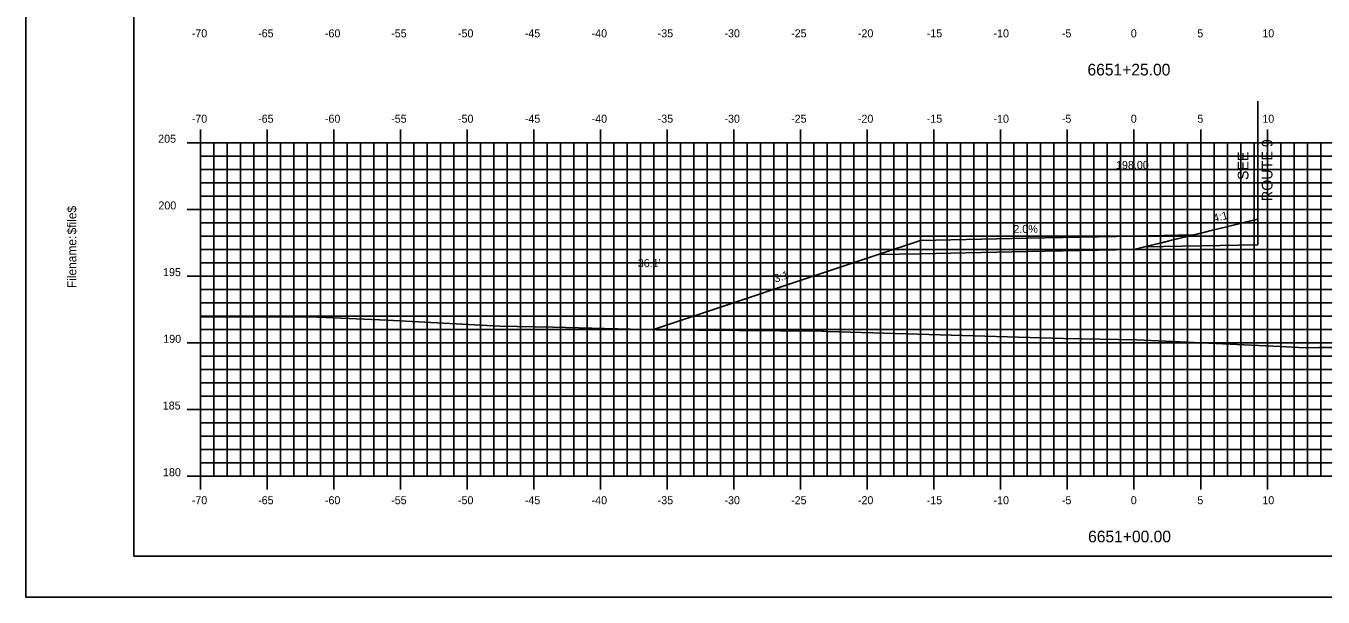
# Model space of a CAD drawing. Extents: x 1723543 to 1723714, y 458501 to 458611.
# Drawn here: x 1723542.7 to 1723640, y 458501.2 to 458544 of the extents above; entities that cross this region are included whole.
import ezdxf

# ---------------------------------------------------------------- set-up
doc = ezdxf.new("R2010")
doc.units = 0
for name, color, linetype in [('ANNOTATION', 7, 'Continuous'), ('BORDER', 7, 'Continuous'), ('D_Roadway_Centerline', 7, 'Continuous'), ('D_Roadway_Centerline_Text', 7, 'Continuous'), ('D_Roadway_Drive_Gravel', 7, 'Continuous'), ('D_Roadway_Edge_Shoulder', 7, 'Continuous'), ('D_Roadway_SlopeLines', 7, 'Continuous'), ('D_Roadway_SubGrade', 7, 'Continuous'), ('D_Text_Standard', 7, 'Continuous'), ('H_V ANNOTATION', 7, 'Continuous'), ('MAJOR', 7, 'Continuous'), ('MINOR', 7, 'Continuous'), ('PLOT BOUNDARY', 7, 'Continuous'), ('S_Roadway_Centerline', 7, 'Continuous')]:
    doc.layers.add(name, color=color, linetype=linetype)

msp = doc.modelspace()

# ---------------------------------------------------------------- linework, layer by layer
msp.add_lwpolyline([(1723589.666, 458521.228), (1723606.594, 458526.871), (1723609.785, 458527.934), (1723617.785, 458528.094), (1723625.785, 458528.254), (1723630.251, 458528.344)])
at = {"layer": 'BORDER'}
msp.add_lwpolyline([(1723550.786, 458504.254), (1723710.786, 458504.254), (1723710.786, 458609.254), (1723550.786, 458609.254)], close=True, dxfattribs=at)
at = {"layer": 'D_Roadway_Centerline'}
msp.add_lwpolyline([(1723625.785, 458527.254), (1723626.585, 458527.449), (1723627.961, 458527.785), (1723628.593, 458527.939), (1723630.323, 458528.361), (1723631.684, 458528.693), (1723632.511, 458528.895), (1723634.424, 458529.362), (1723634.641, 458529.415), (1723635.073, 458529.52)], dxfattribs=at)
at = {"layer": 'D_Roadway_Drive_Gravel'}
msp.add_lwpolyline([(1723625.785, 458528.254), (1723617.785, 458528.094), (1723609.785, 458527.934), (1723606.594, 458526.871), (1723609.785, 458526.934), (1723617.785, 458527.094), (1723625.785, 458527.254), (1723625.785, 458527.254)], dxfattribs=at)
at = {"layer": 'D_Roadway_Edge_Shoulder'}
msp.add_line((1723635.073, 458529.52), (1723635.073, 458529.27), dxfattribs=at)
msp.add_line((1723635.073, 458529.52), (1723635.073, 458529.27), dxfattribs=at)
at = {"layer": 'D_Roadway_SlopeLines'}
for points in [[(1723635.073, 458529.52), (1723625.785, 458527.254)], [(1723635.073, 458529.52), (1723625.785, 458527.254)], [(1723635.073, 458529.52), (1723625.785, 458527.254)], [(1723635.073, 458529.52), (1723625.785, 458527.254)], [(1723635.073, 458529.52), (1723625.785, 458527.254)], [(1723635.073, 458529.52), (1723625.785, 458527.254)], [(1723635.073, 458529.52), (1723625.785, 458527.254)], [(1723635.073, 458529.52), (1723625.785, 458527.254)], [(1723635.073, 458529.52), (1723626.585, 458527.449)], [(1723625.785, 458528.254), (1723630.251, 458528.344)], [(1723609.785, 458527.934), (1723606.594, 458526.871), (1723589.666, 458521.228)]]:
    msp.add_lwpolyline(points, dxfattribs=at)
at = {"layer": 'D_Roadway_SubGrade'}
msp.add_line((1723635.073, 458538.379), (1723635.073, 458527.597), dxfattribs=at)
for points in [[(1723635.073, 458527.597), (1723626.585, 458527.449), (1723635.073, 458529.52), (1723635.073, 458529.27)], [(1723635.073, 458529.27), (1723635.073, 458529.52), (1723626.585, 458527.449), (1723635.073, 458527.597)], [(1723635.073, 458527.597), (1723626.585, 458527.449), (1723635.073, 458529.52), (1723635.073, 458529.27)], [(1723635.073, 458527.597), (1723626.585, 458527.449), (1723635.073, 458529.52), (1723635.073, 458529.27)]]:
    msp.add_lwpolyline(points, dxfattribs=at)
at = {"layer": 'MAJOR'}
for p, q in [((1723555.785, 458536.256), (1723555.785, 458535.254)), ((1723560.785, 458536.256), (1723560.785, 458535.254)), ((1723565.785, 458536.256), (1723565.785, 458535.254)), ((1723570.785, 458536.256), (1723570.785, 458535.254)), ((1723575.785, 458536.256), (1723575.785, 458535.254)), ((1723580.785, 458536.256), (1723580.785, 458535.254)), ((1723585.785, 458536.256), (1723585.785, 458535.254)), ((1723590.785, 458536.256), (1723590.785, 458535.254)), ((1723595.785, 458536.256), (1723595.785, 458535.254)), ((1723600.785, 458536.256), (1723600.785, 458535.254)), ((1723605.785, 458536.256), (1723605.785, 458535.254)), ((1723610.785, 458536.256), (1723610.785, 458535.254)), ((1723615.785, 458536.256), (1723615.785, 458535.254)), ((1723620.785, 458536.256), (1723620.785, 458535.254)), ((1723625.785, 458536.256), (1723625.785, 458535.254)), ((1723630.785, 458536.256), (1723630.785, 458535.254)), ((1723635.785, 458536.256), (1723635.785, 458535.254)), ((1723554.783, 458535.254), (1723555.785, 458535.254)), ((1723555.785, 458535.254), (1723695.785, 458535.254)), ((1723555.785, 458510.254), (1723555.785, 458535.254)), ((1723555.785, 458510.254), (1723555.785, 458535.254)), ((1723555.785, 458535.254), (1723695.785, 458535.254)), ((1723560.785, 458510.254), (1723560.785, 458535.254)), ((1723565.785, 458510.254), (1723565.785, 458535.254)), ((1723570.785, 458510.254), (1723570.785, 458535.254)), ((1723575.785, 458510.254), (1723575.785, 458535.254)), ((1723580.785, 458510.254), (1723580.785, 458535.254)), ((1723585.785, 458510.254), (1723585.785, 458535.254)), ((1723590.785, 458510.254), (1723590.785, 458535.254)), ((1723595.785, 458510.254), (1723595.785, 458535.254)), ((1723600.785, 458510.254), (1723600.785, 458535.254)), ((1723605.785, 458510.254), (1723605.785, 458535.254)), ((1723610.785, 458510.254), (1723610.785, 458535.254)), ((1723615.785, 458510.254), (1723615.785, 458535.254)), ((1723620.785, 458510.254), (1723620.785, 458535.254)), ((1723625.785, 458510.254), (1723625.785, 458535.254)), ((1723630.785, 458510.254), (1723630.785, 458535.254)), ((1723635.785, 458510.254), (1723635.785, 458535.254)), ((1723554.783, 458530.254), (1723555.785, 458530.254)), ((1723555.785, 458530.254), (1723695.785, 458530.254)), ((1723554.783, 458525.254), (1723555.785, 458525.254)), ((1723555.785, 458525.254), (1723695.785, 458525.254)), ((1723554.783, 458520.254), (1723555.785, 458520.254)), ((1723555.785, 458520.254), (1723695.785, 458520.254)), ((1723554.783, 458515.254), (1723555.785, 458515.254)), ((1723555.785, 458515.254), (1723695.785, 458515.254)), ((1723554.783, 458510.254), (1723555.785, 458510.254)), ((1723555.785, 458510.254), (1723695.785, 458510.254)), ((1723555.785, 458510.254), (1723695.785, 458510.254)), ((1723555.785, 458509.252), (1723555.785, 458510.254)), ((1723560.785, 458509.252), (1723560.785, 458510.254)), ((1723565.785, 458509.252), (1723565.785, 458510.254)), ((1723570.785, 458509.252), (1723570.785, 458510.254)), ((1723575.785, 458509.252), (1723575.785, 458510.254)), ((1723580.785, 458509.252), (1723580.785, 458510.254)), ((1723585.785, 458509.252), (1723585.785, 458510.254)), ((1723590.785, 458509.252), (1723590.785, 458510.254)), ((1723595.785, 458509.252), (1723595.785, 458510.254)), ((1723600.785, 458509.252), (1723600.785, 458510.254)), ((1723605.785, 458509.252), (1723605.785, 458510.254)), ((1723610.785, 458509.252), (1723610.785, 458510.254)), ((1723615.785, 458509.252), (1723615.785, 458510.254)), ((1723620.785, 458509.252), (1723620.785, 458510.254)), ((1723625.785, 458509.252), (1723625.785, 458510.254)), ((1723630.785, 458509.252), (1723630.785, 458510.254)), ((1723635.785, 458509.252), (1723635.785, 458510.254))]:
    msp.add_line(p, q, dxfattribs=at)
at = {"layer": 'MINOR'}
for p, q in [((1723556.785, 458510.254), (1723556.785, 458535.254)), ((1723557.785, 458510.254), (1723557.785, 458535.254)), ((1723558.785, 458510.254), (1723558.785, 458535.254)), ((1723559.785, 458510.254), (1723559.785, 458535.254)), ((1723561.785, 458510.254), (1723561.785, 458535.254)), ((1723562.785, 458510.254), (1723562.785, 458535.254)), ((1723563.785, 458510.254), (1723563.785, 458535.254)), ((1723564.785, 458510.254), (1723564.785, 458535.254)), ((1723566.785, 458510.254), (1723566.785, 458535.254)), ((1723567.785, 458510.254), (1723567.785, 458535.254)), ((1723568.785, 458510.254), (1723568.785, 458535.254)), ((1723569.785, 458510.254), (1723569.785, 458535.254)), ((1723571.785, 458510.254), (1723571.785, 458535.254)), ((1723572.785, 458510.254), (1723572.785, 458535.254)), ((1723573.785, 458510.254), (1723573.785, 458535.254)), ((1723574.785, 458510.254), (1723574.785, 458535.254)), ((1723576.785, 458510.254), (1723576.785, 458535.254)), ((1723577.785, 458510.254), (1723577.785, 458535.254)), ((1723578.785, 458510.254), (1723578.785, 458535.254)), ((1723579.785, 458510.254), (1723579.785, 458535.254)), ((1723581.785, 458510.254), (1723581.785, 458535.254)), ((1723582.785, 458510.254), (1723582.785, 458535.254)), ((1723583.785, 458510.254), (1723583.785, 458535.254)), ((1723584.785, 458510.254), (1723584.785, 458535.254)), ((1723586.785, 458510.254), (1723586.785, 458535.254)), ((1723587.785, 458510.254), (1723587.785, 458535.254)), ((1723588.785, 458510.254), (1723588.785, 458535.254)), ((1723589.785, 458510.254), (1723589.785, 458535.254)), ((1723591.785, 458510.254), (1723591.785, 458535.254)), ((1723592.785, 458510.254), (1723592.785, 458535.254)), ((1723593.785, 458510.254), (1723593.785, 458535.254)), ((1723594.785, 458510.254), (1723594.785, 458535.254)), ((1723596.785, 458510.254), (1723596.785, 458535.254)), ((1723597.785, 458510.254), (1723597.785, 458535.254)), ((1723598.785, 458510.254), (1723598.785, 458535.254)), ((1723599.785, 458510.254), (1723599.785, 458535.254)), ((1723601.785, 458510.254), (1723601.785, 458535.254)), ((1723602.785, 458510.254), (1723602.785, 458535.254)), ((1723603.785, 458510.254), (1723603.785, 458535.254)), ((1723604.785, 458510.254), (1723604.785, 458535.254)), ((1723606.785, 458510.254), (1723606.785, 458535.254)), ((1723607.785, 458510.254), (1723607.785, 458535.254)), ((1723608.785, 458510.254), (1723608.785, 458535.254)), ((1723609.785, 458510.254), (1723609.785, 458535.254)), ((1723611.785, 458510.254), (1723611.785, 458535.254)), ((1723612.785, 458510.254), (1723612.785, 458535.254)), ((1723613.785, 458510.254), (1723613.785, 458535.254)), ((1723614.785, 458510.254), (1723614.785, 458535.254)), ((1723616.785, 458510.254), (1723616.785, 458535.254)), ((1723617.785, 458510.254), (1723617.785, 458535.254)), ((1723618.785, 458510.254), (1723618.785, 458535.254)), ((1723619.785, 458510.254), (1723619.785, 458535.254)), ((1723621.785, 458510.254), (1723621.785, 458535.254)), ((1723622.785, 458510.254), (1723622.785, 458535.254)), ((1723623.785, 458510.254), (1723623.785, 458535.254)), ((1723624.785, 458510.254), (1723624.785, 458535.254)), ((1723626.785, 458510.254), (1723626.785, 458535.254)), ((1723627.785, 458510.254), (1723627.785, 458535.254)), ((1723628.785, 458510.254), (1723628.785, 458535.254)), ((1723629.785, 458510.254), (1723629.785, 458535.254)), ((1723631.785, 458510.254), (1723631.785, 458535.254)), ((1723632.785, 458510.254), (1723632.785, 458535.254)), ((1723633.785, 458510.254), (1723633.785, 458535.254)), ((1723634.785, 458510.254), (1723634.785, 458535.254)), ((1723636.785, 458510.254), (1723636.785, 458535.254)), ((1723637.785, 458510.254), (1723637.785, 458535.254)), ((1723638.785, 458510.254), (1723638.785, 458535.254)), ((1723639.785, 458510.254), (1723639.785, 458535.254)), ((1723555.785, 458534.254), (1723695.785, 458534.254)), ((1723555.785, 458534.254), (1723556.787, 458534.254)), ((1723555.785, 458533.254), (1723695.785, 458533.254)), ((1723555.785, 458533.254), (1723556.787, 458533.254)), ((1723555.785, 458532.254), (1723695.785, 458532.254)), ((1723555.785, 458532.254), (1723556.787, 458532.254)), ((1723555.785, 458531.254), (1723695.785, 458531.254)), ((1723555.785, 458531.254), (1723556.787, 458531.254)), ((1723555.785, 458529.254), (1723695.785, 458529.254)), ((1723555.785, 458529.254), (1723556.787, 458529.254)), ((1723555.785, 458528.254), (1723695.785, 458528.254)), ((1723555.785, 458528.254), (1723556.787, 458528.254)), ((1723555.785, 458527.254), (1723695.785, 458527.254)), ((1723555.785, 458527.254), (1723556.787, 458527.254)), ((1723555.785, 458526.254), (1723695.785, 458526.254)), ((1723555.785, 458526.254), (1723556.787, 458526.254)), ((1723555.785, 458524.254), (1723695.785, 458524.254)), ((1723555.785, 458524.254), (1723556.787, 458524.254)), ((1723555.785, 458523.254), (1723695.785, 458523.254)), ((1723555.785, 458523.254), (1723556.787, 458523.254)), ((1723555.785, 458522.254), (1723695.785, 458522.254)), ((1723555.785, 458522.254), (1723556.787, 458522.254)), ((1723555.785, 458521.254), (1723695.785, 458521.254)), ((1723555.785, 458521.254), (1723556.787, 458521.254)), ((1723555.785, 458519.254), (1723695.785, 458519.254)), ((1723555.785, 458519.254), (1723556.787, 458519.254)), ((1723555.785, 458518.254), (1723695.785, 458518.254)), ((1723555.785, 458518.254), (1723556.787, 458518.254)), ((1723555.785, 458517.254), (1723695.785, 458517.254)), ((1723555.785, 458517.254), (1723556.787, 458517.254)), ((1723555.785, 458516.254), (1723695.785, 458516.254)), ((1723555.785, 458516.254), (1723556.787, 458516.254)), ((1723555.785, 458514.254), (1723695.785, 458514.254)), ((1723555.785, 458514.254), (1723556.787, 458514.254)), ((1723555.785, 458513.254), (1723695.785, 458513.254)), ((1723555.785, 458513.254), (1723556.787, 458513.254)), ((1723555.785, 458512.254), (1723695.785, 458512.254)), ((1723555.785, 458512.254), (1723556.787, 458512.254)), ((1723555.785, 458511.254), (1723695.785, 458511.254)), ((1723555.785, 458511.254), (1723556.787, 458511.254))]:
    msp.add_line(p, q, dxfattribs=at)
at = {"layer": 'PLOT BOUNDARY'}
msp.add_lwpolyline([(1723542.692, 458501.195), (1723712.692, 458501.195), (1723712.692, 458611.195), (1723542.692, 458611.195)], close=True, dxfattribs=at)
at = {"layer": 'S_Roadway_Centerline'}
msp.add_lwpolyline([(1723555.785, 458522.191), (1723564.001, 458522.199), (1723565.758, 458522.124), (1723569.789, 458521.964), (1723578.235, 458521.495), (1723582.205, 458521.436), (1723589.984, 458521.219), (1723602.381, 458521.12), (1723602.509, 458521.117), (1723602.82, 458521.11), (1723620.494, 458520.565), (1723626.006, 458520.489), (1723636.736, 458519.983), (1723638.614, 458519.89), (1723639.657, 458519.909), (1723642.964, 458519.912), (1723658.245, 458519.9), (1723662.139, 458519.842), (1723669.988, 458519.439), (1723678.17, 458518.931), (1723686.285, 458518.491), (1723695.453, 458518.097), (1723695.785, 458518.085)], dxfattribs=at)

# ---------------------------------------------------------------- texts
at = {"layer": 'ANNOTATION'}
for s, height, rotation, p in [('ROUTE 9', 0.8, 90, (1723636.17, 458530.878)), ('SEE', 0.8, 90, (1723634.37, 458532.453)), ('4:1', 0.6, 13.61624, (1723631.792, 458529.289)), ('2.0%', 0.6, 1.14576, (1723616.749, 458528.474)), ('3:1', 0.6, 18.43495, (1723598.895, 458524.758))]:
    msp.add_text(s, height=height, rotation=rotation, dxfattribs=at).set_placement(p)
at = {"layer": 'BORDER'}
for s, p in [('$file$', (1723546.47, 458528.38)), ('Filename:', (1723546.47, 458524.353))]:
    msp.add_text(s, height=0.6696, rotation=90, dxfattribs=at).set_placement(p)
at = {"layer": 'D_Roadway_Centerline_Text'}
msp.add_text('198.00', height=0.6, dxfattribs=at).set_placement((1723624.437, 458533.286))
at = {"layer": 'D_Text_Standard'}
msp.add_text("36.1'", height=0.6, dxfattribs=at).set_placement((1723588.572, 458525.928))
at = {"layer": 'H_V ANNOTATION'}
for s, height, p in [('-70', 0.6, (1723555.127, 458543.154)), ('-65', 0.6, (1723560.103, 458543.154)), ('-60', 0.6, (1723565.111, 458543.154)), ('-55', 0.6, (1723570.082, 458543.154)), ('-50', 0.6, (1723575.09, 458543.154)), ('-45', 0.6, (1723580.103, 458543.154)), ('-40', 0.6, (1723585.111, 458543.154)), ('-35', 0.6, (1723590.066, 458543.154)), ('-30', 0.6, (1723595.074, 458543.154)), ('-25', 0.6, (1723600.071, 458543.154)), ('-20', 0.6, (1723605.079, 458543.154)), ('-15', 0.6, (1723610.242, 458543.154)), ('-10', 0.6, (1723615.25, 458543.154)), ('-5', 0.6, (1723620.376, 458543.154)), ('0', 0.6, (1723625.544, 458543.154)), ('5', 0.6, (1723630.536, 458543.154)), ('10', 0.6, (1723635.411, 458543.154)), ('6651+25.00', 0.875, (1723622.297, 458540.297)), ('-70', 0.6, (1723555.127, 458536.754)), ('-65', 0.6, (1723560.103, 458536.754)), ('-60', 0.6, (1723565.111, 458536.754)), ('-55', 0.6, (1723570.082, 458536.754)), ('-50', 0.6, (1723575.09, 458536.754)), ('-45', 0.6, (1723580.103, 458536.754)), ('-40', 0.6, (1723585.111, 458536.754)), ('-35', 0.6, (1723590.066, 458536.754)), ('-30', 0.6, (1723595.074, 458536.754)), ('-25', 0.6, (1723600.071, 458536.754)), ('-20', 0.6, (1723605.079, 458536.754)), ('-15', 0.6, (1723610.242, 458536.754)), ('-10', 0.6, (1723615.25, 458536.754)), ('-5', 0.6, (1723620.376, 458536.754)), ('0', 0.6, (1723625.544, 458536.754)), ('5', 0.6, (1723630.536, 458536.754)), ('10', 0.6, (1723635.411, 458536.754)), ('205', 0.6, (1723552.61, 458535.254)), ('200', 0.6, (1723552.626, 458530.254)), ('195', 0.6, (1723552.974, 458525.254)), ('190', 0.6, (1723552.99, 458520.254)), ('185', 0.6, (1723552.953, 458515.254)), ('180', 0.6, (1723552.969, 458510.254)), ('-70', 0.6, (1723555.127, 458508.154)), ('-65', 0.6, (1723560.103, 458508.154)), ('-60', 0.6, (1723565.111, 458508.154)), ('-55', 0.6, (1723570.082, 458508.154)), ('-50', 0.6, (1723575.09, 458508.154)), ('-45', 0.6, (1723580.103, 458508.154)), ('-40', 0.6, (1723585.111, 458508.154)), ('-35', 0.6, (1723590.066, 458508.154)), ('-30', 0.6, (1723595.074, 458508.154)), ('-25', 0.6, (1723600.071, 458508.154)), ('-20', 0.6, (1723605.079, 458508.154)), ('-15', 0.6, (1723610.242, 458508.154)), ('-10', 0.6, (1723615.25, 458508.154)), ('-5', 0.6, (1723620.376, 458508.154)), ('0', 0.6, (1723625.544, 458508.154)), ('5', 0.6, (1723630.536, 458508.154)), ('10', 0.6, (1723635.411, 458508.154)), ('6651+00.00', 0.875, (1723622.344, 458505.297))]:
    msp.add_text(s, height=height, dxfattribs=at).set_placement(p)
at = {"layer": 'MAJOR'}
msp.add_text('-', height=0.006, dxfattribs=at).set_placement((1723555.781, 458510.254))

doc.saveas('drawing.dxf')
